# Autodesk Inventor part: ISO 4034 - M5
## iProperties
Comments: To add or edit properties for Autodesk Inventor files, use iProperties.
Created: 2004-08
Part Number: ISO 4034 - M5
Vendor: Autodesk Inc.
Document SubType Name: Modeling
Designer: John Blackburn
Material: Default
Description: Hex Nut
Standard: ISO 4034
Alert: To add or edit properties for Autodesk Inventor files, use iProperties.
Control State: 0
Master: False
Checked Out: False
Shininess: 64.0
Length Units: 11269
Angle Units: 11279
Time Units: 11290
Mass Units: 11283
Length Display Precision: 3
Angle Display Precision: 2
Compacted: True
EGR: 1
Density: 0.0
Volumn: 0.0
Area: 0.0
PropertySet Name: Model Information
Author: John Blackburn
Revision Number: 8
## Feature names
1. Body [Extrusion]
2. Chamfer1 [Revolution]
3. Thread [Hole]
4. Chamfer2
5. Chamfer3
